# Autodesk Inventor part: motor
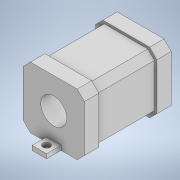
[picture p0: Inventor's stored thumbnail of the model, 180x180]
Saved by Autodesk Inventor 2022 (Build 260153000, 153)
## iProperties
Created: 2021-07
Part Number: motor
Material: Generic
Document SubType Name: Modeling
Designer: 91876
Density: 1 g/cm^3
Appearance: Default
Author: 91876
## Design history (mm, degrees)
sketch "Sketch1"
  geometry: L1 (-12.7, -19.606)-(12.7, -19.606); L2 (19.606, -12.7)-(19.606, 12.7); L3 (-14.971, -19.606)-(-12.7, -19.606); L4 (-19.606, -14.971)-(-14.971, -19.606); L5 (19.606, 12.7)-(19.606, 14.971); L6 (19.606, 14.971)-(14.971, 19.606); L7 (14.971, 19.606)-(12.7, 19.606); L8 (-19.606, -12.7)-(-19.606, -14.971); L9 (-19.606, 12.7)-(-19.606, -12.7); L10 (12.7, 19.606)-(-12.7, 19.606); L11 (-19.606, 14.971)-(-19.606, 12.7); L12 (-12.7, 19.606)-(-14.971, 19.606); L13 (-14.971, 19.606)-(-19.606, 14.971); L14 (12.7, -19.606)-(14.971, -19.606); L15 (19.606, -14.971)-(19.606, -12.7); L16 (14.971, -19.606)-(19.606, -14.971); 2 further points
  constraints: 32 end point
  dimensions: "d2" = 25.4 distance of L7.end L10.end; "d10" = 39.21241 distance between parallel lines of L1 L10
extrude "Extrusion1" new body sketch "Sketch1" distance "d0" = 40; taper "d1" = 0 deg
sketch "Sketch2"
  geometry: 1 further point
sketch "Sketch3"
  geometry: L1 (-21.15, 13.7)-(-21.15, -13.7); L2 (-13.7, -21.15)-(13.7, -21.15); L3 (13.7, -21.15)-(16.15, -21.15); L4 (16.15, -21.15)-(21.15, -16.15); L5 (-21.15, 16.15)-(-21.15, 13.7); L6 (-16.15, 21.15)-(-21.15, 16.15); L7 (21.15, -16.15)-(21.15, -13.7); L8 (-13.7, 21.15)-(-16.15, 21.15); L9 (13.7, 21.15)-(-13.7, 21.15); L10 (16.15, 21.15)-(13.7, 21.15); L11 (21.15, 16.15)-(16.15, 21.15); L12 (21.15, 13.7)-(21.15, 16.15); L13 (21.15, -13.7)-(21.15, 13.7); L14 (-16.15, -21.15)-(-13.7, -21.15); L15 (-21.15, -13.7)-(-21.15, -16.15); L16 (-21.15, -16.15)-(-16.15, -21.15); L17 (-5, -18.062)-(5, -18.062); L18 (5, -18.062)-(5, -21.15); L19 (5, -21.15)-(-5, -21.15); L20 (-5, -21.15)-(-5, -18.062); L21 (-14.971, -19.606)-(14.971, -19.606) reference; L22 (-5, -18.062)-(5, -21.15); L23 (5, -18.062)-(-5, -21.15); 3 further points
  constraints: 44 end point, 3 midpoint, 2 parallel, 1 horizontal, 1 perpendicular, 1 point on line
  dimensions: "d11" = 10 distance of L18.end L19.end
extrude "Extrusion2" join sketch "Sketch3" distance "d3" = 10; taper "d4" = 0 deg
sketch "Sketch4"
  geometry: L1 (-16.15, -21.15)-(-13.7, -21.15); L2 (-21.15, -13.7)-(-21.15, -16.15); L3 (-21.15, -16.15)-(-16.15, -21.15); L4 (-21.15, 13.7)-(-21.15, -13.7); L5 (-13.7, -21.15)-(13.7, -21.15); L6 (13.7, -21.15)-(16.15, -21.15); L7 (16.15, -21.15)-(21.15, -16.15); L8 (-21.15, 16.15)-(-21.15, 13.7); L9 (-16.15, 21.15)-(-21.15, 16.15); L10 (21.15, -16.15)-(21.15, -13.7); L11 (-13.7, 21.15)-(-16.15, 21.15); L12 (21.15, -13.7)-(21.15, 13.7); L13 (13.7, 21.15)-(-13.7, 21.15); L14 (16.15, 21.15)-(13.7, 21.15); L15 (21.15, 13.7)-(21.15, 16.15); L16 (21.15, 16.15)-(16.15, 21.15); 2 further points
  constraints: 32 end point
extrude "Extrusion3" join sketch "Sketch4" distance "d5" = 10; taper "d6" = 0 deg
sketch "Sketch5"
  geometry: C1 r 9 at (0, 0); 1 further point
  constraints: 1 centre point, 1 coincident
  dimensions: "d7" = 18 diameter of C1
extrude "Extrusion4" cut sketch "Sketch5" extent not by distance; stored distance "d8" = 0; taper "d9" = 0 deg
sketch "Sketch8"
  geometry: L1 (-16.15, -21.15)-(16.15, -21.15) reference; L2 (-5, -18.062)-(5, -18.062); L3 (5, -18.062)-(5, -21.15); L4 (5, -21.15)-(-5, -21.15); L5 (-5, -21.15)-(-5, -18.062); L6 (-14.971, -19.606)-(14.971, -19.606) reference; L7 (-5, -18.062)-(5, -21.15); L8 (5, -18.062)-(-5, -21.15); 3 further points
  constraints: 12 end point, 3 midpoint, 2 parallel, 1 horizontal, 1 perpendicular, 1 point on line
  dimensions: "d12" = 10 distance of L3.end L4.end
extrude "Extrusion5" join sketch "Sketch8" distance "d13" = 10; taper "d14" = 0 deg
sketch "Sketch9"
  geometry: L1 (21.15, 0)-(-11.15, 0) reference; L2 (0, 0)-(0, -10) reference; 2 further points
  dimensions: "d22" = 5 distance from line of L1 point (5, -5); "d23" = 5 distance from line of L2 point (5, -5)
hole "Hole1" sketch "Sketch9" at (5, -5) diameter "d15" = 5; stored, may be unused: countersink angle "d19" = 90 deg, drill point angle "d21" = 118 deg; dims "d16" = 6, "d17" = 4, "d18" = 2, "d20" = 8
body "Solid1"
